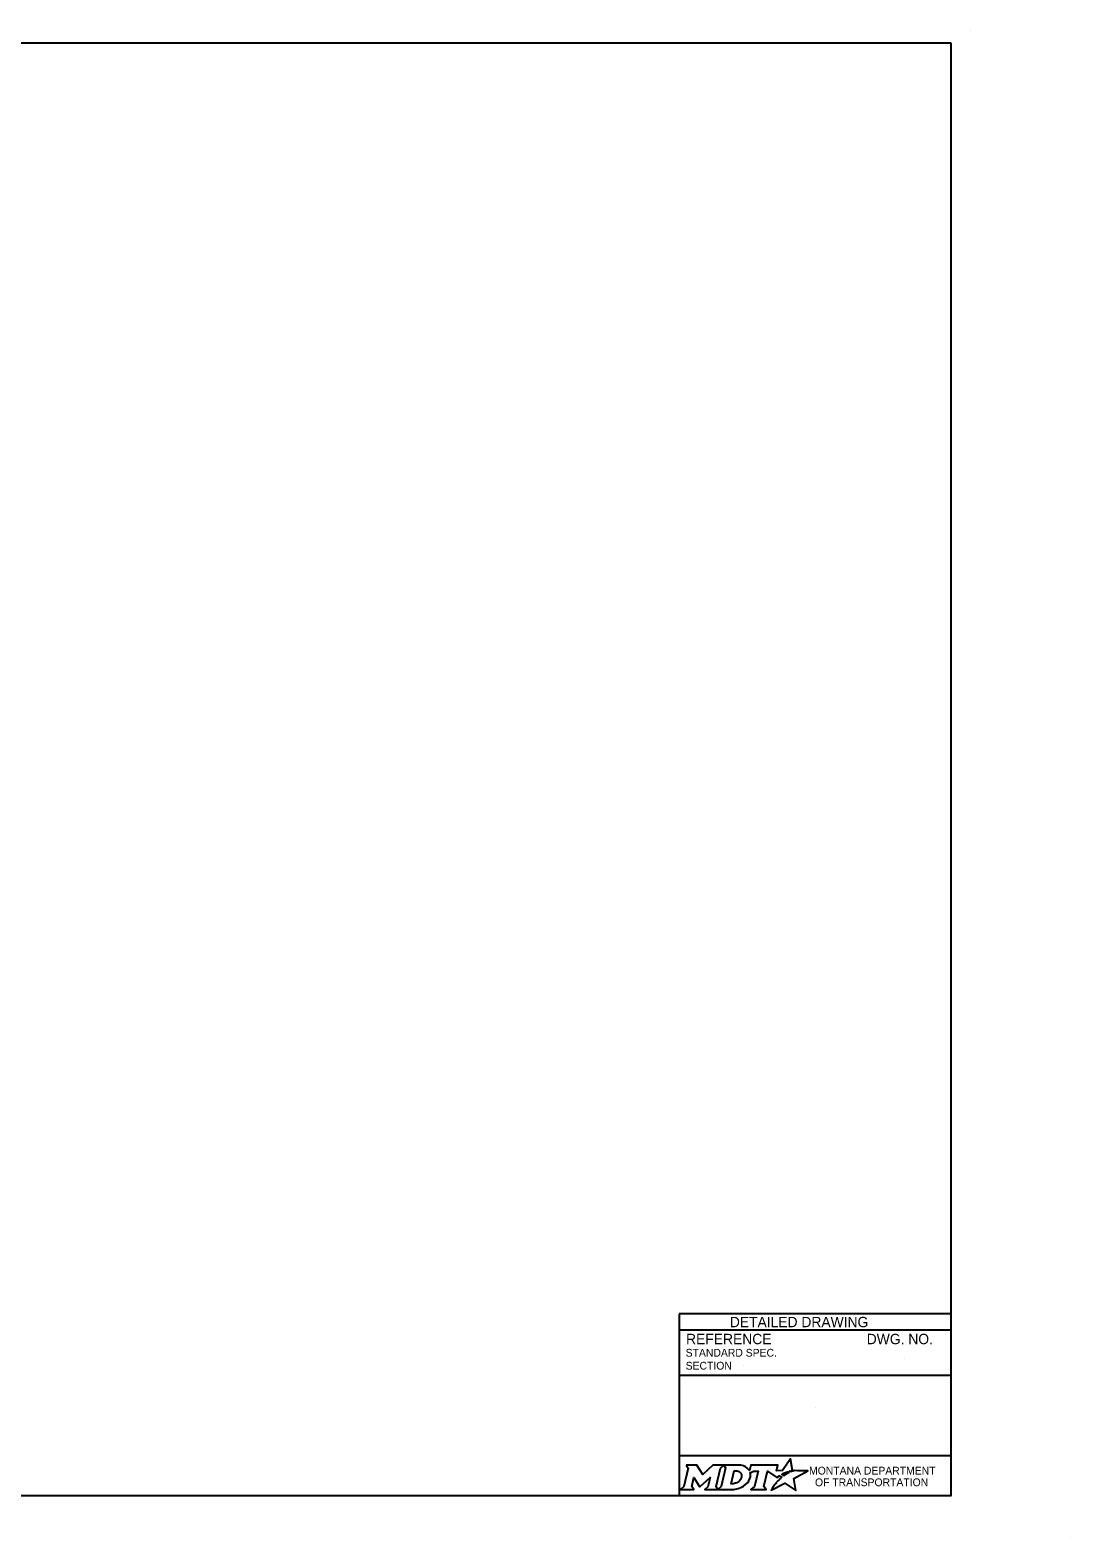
# Model space of a CAD drawing. Extents: x 49983 to 50021, y 49963.5 to 50011.4.
# Drawn here: x 50001.51 to 50009.54, y 49999.74 to 50011.36 of the extents above; entities that cross this region are included whole.
import ezdxf

# ---------------------------------------------------------------- set-up
doc = ezdxf.new("R2010")
doc.units = 0
doc.layers.add('Level 1', color=7, linetype='Continuous')
doc.layers.add('Level 2', color=7, linetype='Continuous')

msp = doc.modelspace()

# ---------------------------------------------------------------- linework, layer by layer
at = {"layer": 'Level 1'}
for p, q in [((50008.765, 50011.363), (50008.765, 50011.363)), ((50009.537, 49999.736), (50009.537, 49999.736))]:
    msp.add_line(p, q, dxfattribs=at)
msp.add_lwpolyline([(50008.615, 50011.263), (50000.336, 50011.263), (50000.336, 50000.062), (50008.615, 50000.062)], close=True, dxfattribs=at)
at = {"layer": 'Level 2'}
for p, q in [((50008.615, 50001.462), (50006.515, 50001.462)), ((50006.515, 50001.462), (50006.515, 50000.062)), ((50008.615, 50001.337), (50006.515, 50001.337)), ((50007.009, 50001.063), (50007.009, 50001.063)), ((50008.251, 50001.122), (50008.251, 50001.122)), ((50008.615, 50000.987), (50006.515, 50000.987)), ((50007.565, 50000.738), (50007.565, 50000.738)), ((50008.615, 50000.369), (50006.515, 50000.369))]:
    msp.add_line(p, q, dxfattribs=at)
for points in [[(50007.377, 50000.245), (50007.367, 50000.25), (50007.378, 50000.253), (50007.39, 50000.255), (50007.373, 50000.345), (50007.313, 50000.254), (50007.266, 50000.253), (50007.276, 50000.297), (50007.067, 50000.297), (50007.057, 50000.255), (50007.051, 50000.263)], [(50006.57, 50000.297), (50006.584, 50000.274), (50006.551, 50000.131), (50006.525, 50000.108), (50006.627, 50000.108), (50006.613, 50000.131), (50006.629, 50000.201), (50006.673, 50000.132), (50006.678, 50000.132), (50006.753, 50000.202), (50006.737, 50000.13), (50006.712, 50000.108), (50006.814, 50000.108), (50006.8, 50000.132), (50006.833, 50000.274)], [(50006.833, 50000.274), (50006.859, 50000.297), (50006.776, 50000.297), (50006.697, 50000.224), (50006.652, 50000.297), (50006.57, 50000.297)], [(50006.972, 50000.297), (50006.859, 50000.297), (50006.873, 50000.275), (50006.839, 50000.131), (50006.814, 50000.108), (50006.925, 50000.108)], [(50006.996, 50000.211), (50006.995, 50000.203), (50006.992, 50000.193), (50006.988, 50000.185), (50006.982, 50000.178), (50006.976, 50000.171), (50006.968, 50000.164), (50006.959, 50000.16), (50006.95, 50000.156), (50006.941, 50000.154), (50006.932, 50000.153), (50006.916, 50000.153), (50006.94, 50000.253), (50006.956, 50000.253), (50006.963, 50000.252), (50006.971, 50000.25), (50006.977, 50000.247), (50006.983, 50000.243), (50006.988, 50000.238), (50006.992, 50000.232), (50006.995, 50000.226), (50006.996, 50000.218), (50006.996, 50000.215), (50006.996, 50000.211)], [(50007.064, 50000.238), (50007.088, 50000.251), (50007.125, 50000.251), (50007.097, 50000.131), (50007.069, 50000.108), (50007.185, 50000.108), (50007.168, 50000.131), (50007.196, 50000.251), (50007.268, 50000.2), (50007.289, 50000.215), (50007.309, 50000.204)], [(50007.253, 50000.148), (50007.237, 50000.124), (50007.233, 50000.116), (50007.227, 50000.107), (50007.225, 50000.103), (50007.33, 50000.156), (50007.414, 50000.101), (50007.401, 50000.194), (50007.508, 50000.252), (50007.458, 50000.253), (50007.428, 50000.253), (50007.407, 50000.254), (50007.401, 50000.252), (50007.396, 50000.251), (50007.387, 50000.249), (50007.377, 50000.245)], [(50007.327, 50000.217), (50007.324, 50000.215), (50007.306, 50000.225), (50007.316, 50000.231), (50007.32, 50000.233), (50007.329, 50000.237), (50007.335, 50000.239), (50007.343, 50000.243), (50007.35, 50000.245), (50007.362, 50000.238), (50007.358, 50000.236), (50007.353, 50000.233), (50007.349, 50000.231), (50007.344, 50000.228), (50007.342, 50000.227), (50007.339, 50000.225), (50007.337, 50000.224), (50007.334, 50000.222), (50007.332, 50000.221), (50007.329, 50000.219), (50007.327, 50000.217)], [(50006.97, 50000.116), (50006.979, 50000.118), (50006.992, 50000.124), (50007.012, 50000.135)], [(50007.267, 50000.164), (50007.267, 50000.164)]]:
    msp.add_lwpolyline(points, dxfattribs=at)
for centre, radius, start, end in [((50006.995, 50000.219), 0.0709, 339.5329, 15.8582), ((50006.951, 50000.236), 0.118, 300.9103, 339.1383)]:
    msp.add_arc(centre, radius, start, end, dxfattribs=at)
for centre, major_axis, ratio, start_param, end_param in [((50006.97, 50000.25), (0.0834, -0.0037), 0.568097, 0.61298, 1.570796), ((50007.026, 50000.257), (0.0361, -0.0295), 0.469099, 1.225588, 1.570796), ((50006.925, 50000.257), (0, 0.148), 0.987302, 3.139398, 3.456847), ((50007.26, 50000.156), (-0.00694, -0.00806), 0.008222, 0, 3.137361), ((50007.276, 50000.174), (-0.0098, -0.0102), 0.016458, 3.141593, 6.279097), ((50007.297, 50000.194), (-0.0112, -0.0097), 0.021651, 3.157348, 6.283185)]:
    msp.add_ellipse(centre, major_axis=major_axis, ratio=ratio, start_param=start_param, end_param=end_param, dxfattribs=at)

# ---------------------------------------------------------------- texts
for s, height, p in [('DETAILED DRAWING', 0.0799, (50006.906, 50001.36)), ('REFERENCE', 0.08, (50006.568, 50001.229)), ('DWG. NO.', 0.08, (50007.962, 50001.229)), ('STANDARD SPEC.', 0.06, (50006.565, 50001.133)), ('SECTION', 0.06, (50006.565, 50001.033))]:
    msp.add_text(s, height=height, dxfattribs=at).set_placement(p)
for s, p in [('MONTANA DEPARTMENT', (50007.517, 50000.224)), ('OF TRANSPORTATION', (50007.563, 50000.134))]:
    msp.add_text(s, height=0.06, rotation=360, dxfattribs=at).set_placement(p)

doc.saveas('drawing.dxf')
